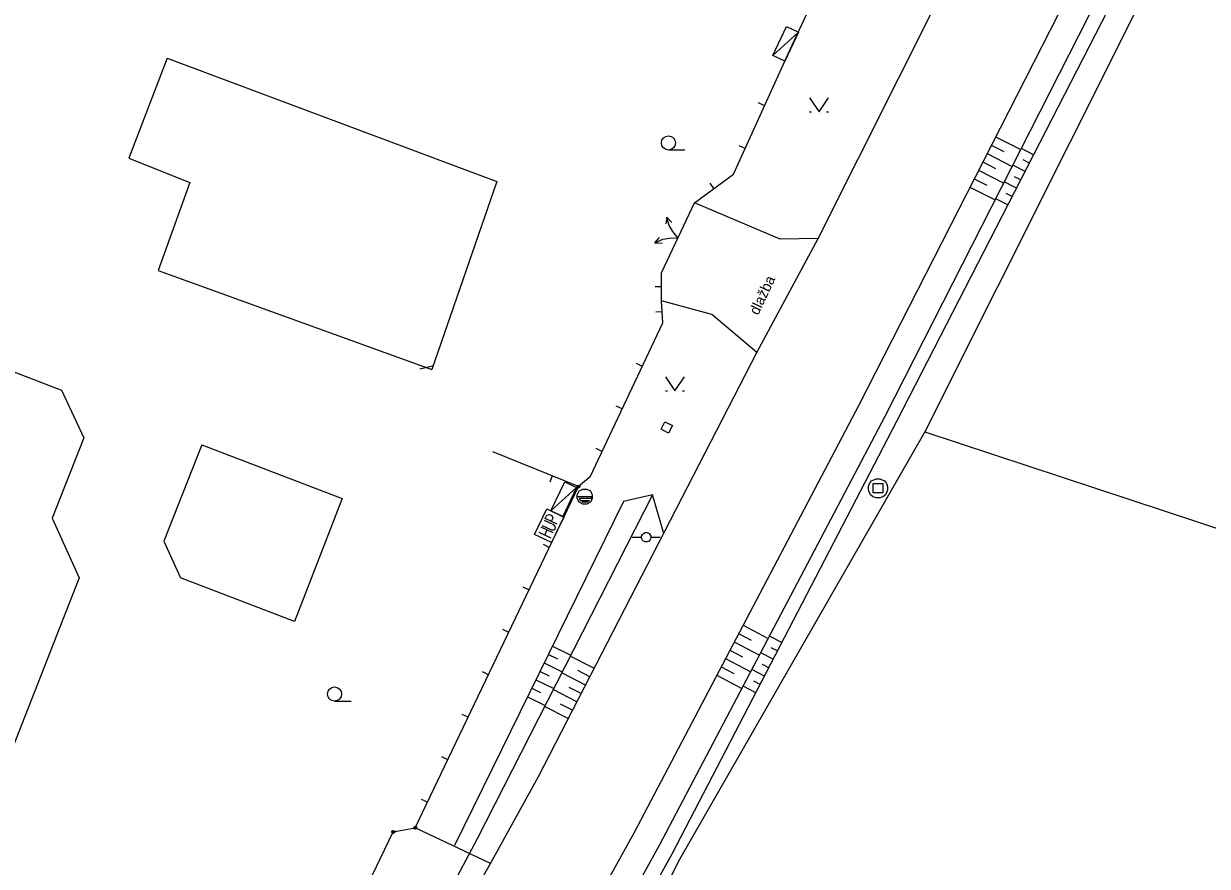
# Model space of a CAD drawing. Extents: x -559554 to -559082, y -1075950 to -1075150.
# Drawn here: x -559443.6 to -559380.7, y -1075743.2 to -1075698.4 of the extents above; entities that cross this region are included whole.
import ezdxf

# ---------------------------------------------------------------- set-up
doc = ezdxf.new("R2010")
doc.units = 0
doc.layers.add('kl', color=7, linetype='Continuous')
doc.layers.add('PF', color=7, linetype='Continuous')

msp = doc.modelspace()

# ---------------------------------------------------------------- linework, layer by layer
at = {"layer": 'kl'}
for p, q in [((-559402.78, -1075699.61), (-559397.1, -1075687.39)), ((-559386.529, -1075693.78), (-559399.214, -1075718.658)), ((-559397.813, -1075719.242), (-559385.226, -1075694.512)), ((-559397.195, -1075719.521), (-559384.5, -1075694.796)), ((-559401.36, -1075709.81), (-559394.036, -1075695.188)), ((-559383.963, -1075696.632), (-559395.705, -1075720.081)), ((-559403.774, -1075700.089), (-559403.05, -1075698.551)), ((-559403.774, -1075700.089), (-559402.417, -1075698.849)), ((-559402.417, -1075698.849), (-559403.141, -1075700.387)), ((-559403.05, -1075698.551), (-559402.417, -1075698.849)), ((-559405.87, -1075706.4), (-559402.78, -1075699.61)), ((-559403.141, -1075700.387), (-559403.774, -1075700.089)), ((-559404.213, -1075702.759), (-559404.531, -1075702.614)), ((-559401.822, -1075702.341), (-559401.322, -1075703.091)), ((-559401.322, -1075703.091), (-559400.822, -1075702.341)), ((-559401.822, -1075703.091), (-559401.722, -1075703.091)), ((-559400.922, -1075703.091), (-559400.822, -1075703.091)), ((-559391.948, -1075704.407), (-559390.609, -1075705.089)), ((-559409.317, -1075705.11), (-559408.442, -1075705.11)), ((-559405.248, -1075705.034), (-559405.567, -1075704.889)), ((-559392.175, -1075704.852), (-559391.506, -1075705.194)), ((-559389.925, -1075705.363), (-559390.578, -1075705.028)), ((-559392.629, -1075705.743), (-559391.959, -1075706.085)), ((-559392.402, -1075705.298), (-559391.063, -1075705.981)), ((-559390.154, -1075705.808), (-559390.479, -1075705.641)), ((-559407.93, -1075707.91), (-559405.87, -1075706.4)), ((-559392.856, -1075706.189), (-559391.517, -1075706.872)), ((-559390.382, -1075706.253), (-559391.032, -1075705.919)), ((-559406.9, -1075707.155), (-559407.106, -1075706.872)), ((-559393.31, -1075707.08), (-559391.97, -1075707.763)), ((-559393.083, -1075706.634), (-559392.413, -1075706.976)), ((-559390.839, -1075707.142), (-559391.485, -1075706.81)), ((-559390.611, -1075706.698), (-559390.935, -1075706.531)), ((-559391.296, -1075708.032), (-559391.939, -1075707.702)), ((-559391.067, -1075707.587), (-559391.39, -1075707.422)), ((-559409.68, -1075711.63), (-559407.93, -1075707.91)), ((-559403.39, -1075709.85), (-559407.93, -1075707.91)), ((-559409.397, -1075708.68), (-559409.456, -1075709.039)), ((-559409.275, -1075709.124), (-559409.397, -1075708.68)), ((-559409.397, -1075708.68), (-559409.144, -1075708.965)), ((-559409.088, -1075709.433), (-559409.275, -1075709.124)), ((-559408.811, -1075709.784), (-559409.088, -1075709.433)), ((-559410.036, -1075710.037), (-559409.796, -1075709.763)), ((-559410.036, -1075710.037), (-559409.615, -1075709.848)), ((-559410.036, -1075710.037), (-559409.655, -1075710.051)), ((-559409.615, -1075709.848), (-559409.259, -1075709.795)), ((-559409.259, -1075709.795), (-559408.811, -1075709.784)), ((-559404.62, -1075715.86), (-559401.36, -1075709.81)), ((-559401.36, -1075709.81), (-559403.39, -1075709.85)), ((-559409.68, -1075713.12), (-559409.68, -1075711.63)), ((-559409.68, -1075712.375), (-559410.03, -1075712.375)), ((-559409.61, -1075714.29), (-559409.68, -1075713.12)), ((-559407.01, -1075713.85), (-559409.68, -1075713.12)), ((-559409.645, -1075713.705), (-559409.994, -1075713.725)), ((-559404.62, -1075715.86), (-559407.01, -1075713.85)), ((-559413.48, -1075722.48), (-559409.61, -1075714.29)), ((-559416.222, -1075738.383), (-559404.62, -1075715.86)), ((-559410.703, -1075716.603), (-559411.019, -1075716.453)), ((-559422.512, -1075716.738), (-559421.844, -1075716.578)), ((-559409.473, -1075717.155), (-559408.973, -1075717.905)), ((-559408.973, -1075717.905), (-559408.473, -1075717.155)), ((-559409.473, -1075717.905), (-559409.373, -1075717.905)), ((-559408.573, -1075717.905), (-559408.473, -1075717.905)), ((-559411.771, -1075718.863), (-559412.087, -1075718.713)), ((-559399.214, -1075718.658), (-559411.156, -1075741.393)), ((-559409.789, -1075742.037), (-559397.813, -1075719.242)), ((-559409.711, -1075719.945), (-559409.507, -1075719.544)), ((-559409.507, -1075719.544), (-559409.106, -1075719.748)), ((-559409.112, -1075742.5), (-559397.195, -1075719.521)), ((-559409.31, -1075720.149), (-559409.711, -1075719.945)), ((-559409.106, -1075719.748), (-559409.31, -1075720.149)), ((-559395.705, -1075720.081), (-559408.734, -1075742.801)), ((-559395.705, -1075720.081), (-559373.375, -1075727.466)), ((-559414.1, -1075722.99), (-559418.647, -1075721.138)), ((-559412.839, -1075721.123), (-559413.155, -1075720.974)), ((-559415.489, -1075722.424), (-559415.621, -1075722.748)), ((-559415.557, -1075724.277), (-559414.824, -1075722.743)), ((-559414.824, -1075722.743), (-559414.192, -1075723.045)), ((-559413.48, -1075722.48), (-559414.1, -1075722.99)), ((-559398.641, -1075722.829), (-559398.541, -1075722.679)), ((-559398.541, -1075722.679), (-559398.291, -1075722.579)), ((-559398.291, -1075722.579), (-559398.091, -1075722.579)), ((-559398.091, -1075722.579), (-559397.841, -1075722.679)), ((-559397.841, -1075722.679), (-559397.741, -1075722.829)), ((-559422.76, -1075741.11), (-559414.1, -1075722.99)), ((-559410.16, -1075723.42), (-559419.48, -1075741.7)), ((-559415.557, -1075724.277), (-559414.192, -1075723.045)), ((-559414.192, -1075723.045), (-559414.925, -1075724.579)), ((-559414.16, -1075723.42), (-559414.06, -1075723.22)), ((-559414.16, -1075723.62), (-559414.16, -1075723.42)), ((-559414.155, -1075722.99), (-559414.144, -1075722.968)), ((-559414.065, -1075723.034), (-559414.155, -1075722.99)), ((-559414.144, -1075722.968), (-559414.054, -1075723.011)), ((-559414.144, -1075723.024), (-559414.098, -1075723.046)), ((-559414.133, -1075722.946), (-559414.1, -1075722.934)), ((-559414.043, -1075722.989), (-559414.133, -1075722.946)), ((-559414.1, -1075722.934), (-559414.055, -1075722.956)), ((-559414.098, -1075723.046), (-559414.065, -1075723.034)), ((-559414.06, -1075723.22), (-559413.86, -1075723.12)), ((-559414.054, -1075723.011), (-559414.043, -1075722.989)), ((-559413.86, -1075723.12), (-559413.66, -1075723.12)), ((-559413.66, -1075723.12), (-559413.46, -1075723.22)), ((-559413.46, -1075723.22), (-559413.36, -1075723.42)), ((-559413.36, -1075723.42), (-559413.36, -1075723.62)), ((-559410.16, -1075723.42), (-559411.7, -1075723.79)), ((-559409.56, -1075725.49), (-559410.16, -1075723.42)), ((-559398.691, -1075722.979), (-559398.641, -1075722.829)), ((-559398.691, -1075723.179), (-559398.691, -1075722.979)), ((-559398.591, -1075723.429), (-559398.691, -1075723.179)), ((-559398.441, -1075723.529), (-559398.591, -1075723.429)), ((-559398.441, -1075722.829), (-559397.941, -1075722.829)), ((-559398.441, -1075723.329), (-559398.441, -1075722.829)), ((-559397.941, -1075723.329), (-559398.441, -1075723.329)), ((-559397.941, -1075722.829), (-559397.941, -1075723.329)), ((-559397.791, -1075723.429), (-559397.941, -1075723.529)), ((-559397.691, -1075723.179), (-559397.791, -1075723.429)), ((-559397.741, -1075722.829), (-559397.691, -1075722.979)), ((-559397.691, -1075722.979), (-559397.691, -1075723.179)), ((-559411.7, -1075723.79), (-559420.68, -1075742.05)), ((-559414.16, -1075723.52), (-559413.36, -1075723.52)), ((-559414.06, -1075723.82), (-559414.16, -1075723.62)), ((-559413.46, -1075723.62), (-559414.06, -1075723.62)), ((-559414.06, -1075723.62), (-559414.01, -1075723.72)), ((-559413.86, -1075723.92), (-559414.06, -1075723.82)), ((-559414.01, -1075723.72), (-559413.51, -1075723.72)), ((-559413.61, -1075723.82), (-559413.91, -1075723.82)), ((-559413.66, -1075723.92), (-559413.86, -1075723.92)), ((-559413.46, -1075723.82), (-559413.66, -1075723.92)), ((-559413.51, -1075723.72), (-559413.61, -1075723.82)), ((-559413.36, -1075723.52), (-559413.46, -1075723.62)), ((-559413.36, -1075723.62), (-559413.46, -1075723.82)), ((-559398.291, -1075723.579), (-559398.441, -1075723.529)), ((-559398.091, -1075723.579), (-559398.291, -1075723.579)), ((-559397.941, -1075723.529), (-559398.091, -1075723.579)), ((-559416.422, -1075725.53), (-559415.775, -1075724.177)), ((-559415.855, -1075724.692), (-559415.769, -1075724.512)), ((-559415.775, -1075724.177), (-559414.873, -1075724.608)), ((-559415.769, -1075724.512), (-559415.636, -1075724.465)), ((-559415.636, -1075724.465), (-559415.501, -1075724.53)), ((-559414.925, -1075724.579), (-559415.557, -1075724.277)), ((-559415.453, -1075724.663), (-559415.54, -1075724.843)), ((-559414.873, -1075724.608), (-559415.52, -1075725.961)), ((-559415.501, -1075724.53), (-559415.453, -1075724.663)), ((-559415.439, -1075725.445), (-559416.071, -1075725.144)), ((-559416.028, -1075725.053), (-559415.532, -1075725.29)), ((-559415.402, -1075725.02), (-559415.899, -1075724.783)), ((-559415.885, -1075725.565), (-559415.755, -1075725.294)), ((-559415.224, -1075724.994), (-559415.855, -1075724.692)), ((-559415.532, -1075725.29), (-559415.42, -1075725.288)), ((-559415.42, -1075725.288), (-559415.353, -1075725.265)), ((-559415.334, -1075725.108), (-559415.402, -1075725.02)), ((-559415.353, -1075725.265), (-559415.31, -1075725.175)), ((-559415.31, -1075725.175), (-559415.334, -1075725.108)), ((-559415.52, -1075725.961), (-559416.422, -1075725.53)), ((-559416.2, -1075725.414), (-559415.569, -1075725.716)), ((-559411.25, -1075725.68), (-559410.75, -1075725.68)), ((-559410.75, -1075725.63), (-559410.7, -1075725.53)), ((-559410.75, -1075725.73), (-559410.75, -1075725.63)), ((-559410.7, -1075725.83), (-559410.75, -1075725.73)), ((-559410.7, -1075725.53), (-559410.65, -1075725.48)), ((-559410.65, -1075725.88), (-559410.7, -1075725.83)), ((-559410.65, -1075725.48), (-559410.55, -1075725.43)), ((-559410.55, -1075725.93), (-559410.65, -1075725.88)), ((-559410.55, -1075725.43), (-559410.45, -1075725.43)), ((-559410.45, -1075725.93), (-559410.55, -1075725.93)), ((-559410.45, -1075725.43), (-559410.35, -1075725.48)), ((-559410.35, -1075725.88), (-559410.45, -1075725.93)), ((-559410.35, -1075725.48), (-559410.3, -1075725.53)), ((-559410.3, -1075725.83), (-559410.35, -1075725.88)), ((-559410.3, -1075725.53), (-559410.25, -1075725.63)), ((-559410.25, -1075725.73), (-559410.3, -1075725.83)), ((-559410.25, -1075725.63), (-559410.25, -1075725.73)), ((-559410.25, -1075725.68), (-559409.75, -1075725.68)), ((-559415.645, -1075726.222), (-559415.96, -1075726.071)), ((-559416.723, -1075728.478), (-559417.038, -1075728.327)), ((-559417.801, -1075730.734), (-559418.116, -1075730.583)), ((-559405.59, -1075730.797), (-559404.922, -1075731.149)), ((-559405.358, -1075730.355), (-559404.02, -1075731.057)), ((-559403.292, -1075731.278), (-559403.955, -1075730.934)), ((-559415.472, -1075731.461), (-559414.503, -1075731.938)), ((-559405.823, -1075731.24), (-559404.485, -1075731.942)), ((-559403.522, -1075731.722), (-559403.855, -1075731.549)), ((-559415.693, -1075731.91), (-559415.211, -1075732.147)), ((-559413.272, -1075732.642), (-559414.532, -1075731.995)), ((-559406.288, -1075732.125), (-559404.95, -1075732.828)), ((-559406.055, -1075731.683), (-559405.387, -1075732.034)), ((-559403.752, -1075732.165), (-559404.42, -1075731.819)), ((-559418.879, -1075732.989), (-559419.194, -1075732.838)), ((-559416.134, -1075732.807), (-559415.659, -1075733.041)), ((-559415.914, -1075732.358), (-559414.957, -1075732.829)), ((-559413.5, -1075733.087), (-559414.13, -1075732.763)), ((-559406.52, -1075732.568), (-559405.852, -1075732.919)), ((-559404.212, -1075733.053), (-559404.885, -1075732.704)), ((-559403.982, -1075732.609), (-559404.318, -1075732.435)), ((-559416.355, -1075733.256), (-559415.411, -1075733.72)), ((-559413.729, -1075733.531), (-559414.986, -1075732.886)), ((-559406.753, -1075733.011), (-559405.416, -1075733.713)), ((-559404.443, -1075733.497), (-559404.78, -1075733.322)), ((-559416.575, -1075733.704), (-559416.107, -1075733.935)), ((-559414.186, -1075734.421), (-559415.44, -1075733.776)), ((-559413.958, -1075733.976), (-559414.585, -1075733.654)), ((-559404.673, -1075733.941), (-559405.351, -1075733.589)), ((-559427.049, -1075734.383), (-559426.174, -1075734.383)), ((-559416.796, -1075734.153), (-559415.865, -1075734.611)), ((-559414.643, -1075735.31), (-559415.894, -1075734.667)), ((-559414.415, -1075734.866), (-559415.041, -1075734.544)), ((-559419.957, -1075735.245), (-559420.272, -1075735.094)), ((-559421.035, -1075737.501), (-559421.35, -1075737.35)), ((-559418.77, -1075743.01), (-559416.222, -1075738.383)), ((-559422.113, -1075739.756), (-559422.428, -1075739.605)), ((-559426.92, -1075747.52), (-559423.93, -1075741.33)), ((-559411.156, -1075741.393), (-559424.321, -1075765.158)), ((-559423.985, -1075741.33), (-559423.974, -1075741.308)), ((-559423.895, -1075741.374), (-559423.985, -1075741.33)), ((-559423.974, -1075741.308), (-559423.884, -1075741.351)), ((-559423.974, -1075741.364), (-559423.928, -1075741.386)), ((-559423.963, -1075741.286), (-559423.93, -1075741.274)), ((-559423.873, -1075741.329), (-559423.963, -1075741.286)), ((-559423.93, -1075741.33), (-559422.76, -1075741.11)), ((-559423.93, -1075741.274), (-559423.885, -1075741.296)), ((-559423.928, -1075741.386), (-559423.895, -1075741.374)), ((-559423.884, -1075741.351), (-559423.873, -1075741.329)), ((-559422.815, -1075741.11), (-559422.804, -1075741.088)), ((-559422.725, -1075741.154), (-559422.815, -1075741.11)), ((-559422.804, -1075741.088), (-559422.714, -1075741.131)), ((-559422.804, -1075741.144), (-559422.758, -1075741.166)), ((-559422.793, -1075741.066), (-559422.76, -1075741.054)), ((-559422.703, -1075741.109), (-559422.793, -1075741.066)), ((-559422.76, -1075741.054), (-559422.715, -1075741.076)), ((-559418.77, -1075743.01), (-559422.76, -1075741.11)), ((-559422.758, -1075741.166), (-559422.725, -1075741.154)), ((-559422.714, -1075741.131), (-559422.703, -1075741.109)), ((-559419.48, -1075741.7), (-559424.28, -1075750.77)), ((-559422.993, -1075765.867), (-559409.789, -1075742.037)), ((-559422.428, -1075766.103), (-559409.112, -1075742.5)), ((-559408.734, -1075742.801), (-559421.047, -1075766.927)), ((-559422.92, -1075750.32), (-559418.77, -1075743.01))]:
    msp.add_line(p, q, dxfattribs=at)
for centre, radius in [((-559409.317, -1075704.736), 0.375), ((-559414.1, -1075722.99), 0.075), ((-559427.049, -1075734.009), 0.375), ((-559423.93, -1075741.33), 0.075), ((-559422.76, -1075741.11), 0.075)]:
    msp.add_circle(centre, radius, dxfattribs=at)
at = {"layer": 'PF'}
for p, q in [((-559435.939, -1075700.229), (-559437.969, -1075705.537)), ((-559435.939, -1075700.229), (-559418.43, -1075706.785)), ((-559437.969, -1075705.537), (-559434.737, -1075706.83)), ((-559434.737, -1075706.83), (-559436.415, -1075711.503)), ((-559418.43, -1075706.785), (-559421.875, -1075716.768)), ((-559436.415, -1075711.503), (-559421.875, -1075716.768)), ((-559452.936, -1075713.51), (-559441.549, -1075717.87)), ((-559441.549, -1075717.87), (-559440.36, -1075720.401)), ((-559440.36, -1075720.401), (-559442.05, -1075724.67)), ((-559434.1, -1075720.78), (-559436.12, -1075725.89)), ((-559434.1, -1075720.78), (-559426.64, -1075723.63)), ((-559426.64, -1075723.63), (-559429.18, -1075730.16)), ((-559442.05, -1075724.67), (-559440.6, -1075727.83)), ((-559436.12, -1075725.89), (-559435.229, -1075727.83)), ((-559440.6, -1075727.83), (-559444.851, -1075738.639)), ((-559429.18, -1075730.16), (-559435.229, -1075727.83))]:
    msp.add_line(p, q, dxfattribs=at)

# ---------------------------------------------------------------- texts
at = {"layer": 'kl'}
msp.add_text('dlažba', height=0.5525, rotation=64.80629, dxfattribs=at).set_placement((-559404.555, -1075713.918))

doc.saveas('drawing.dxf')
